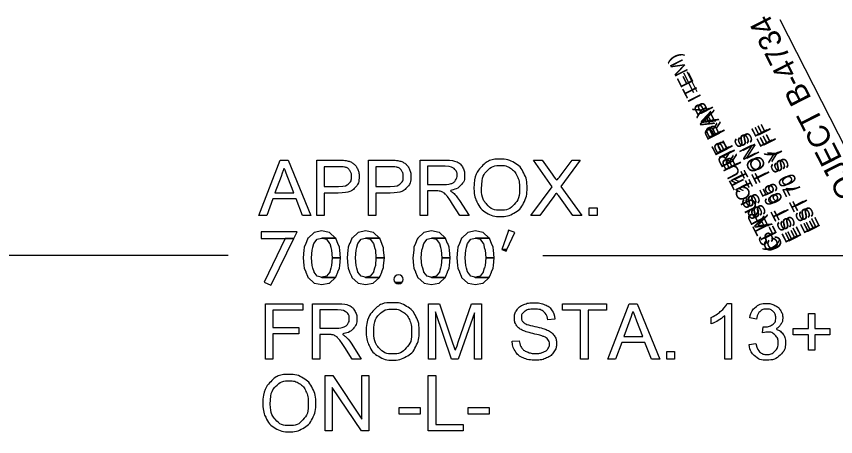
# Model space of a CAD drawing. Extents: x 557583 to 560285, y 513145 to 516544.
# Drawn here: x 558916.3 to 559211.5, y 515124.2 to 515275.7 of the extents above; entities that cross this region are included whole.
import ezdxf

# ---------------------------------------------------------------- set-up
doc = ezdxf.new("R2010")
doc.units = 0
for name, color, linetype in [('Default', 7, 'Continuous'), ('Prop Dimension', 7, 'Continuous'), ('Prop DSN Text', 7, 'Continuous'), ('Scratch_Level_0', 7, 'Continuous')]:
    doc.layers.add(name, color=color, linetype=linetype)

msp = doc.modelspace()

# ---------------------------------------------------------------- linework, layer by layer
at = {"layer": 'Default'}
for p, q in [((559160.44, 515248.11), (559156.81, 515255.24)), ((559161.62, 515248.55), (559157.99, 515255.68)), ((558992.61, 515189.47), (558699.28, 515189.47)), ((559105.95, 515189.47), (559399.28, 515189.47))]:
    msp.add_line(p, q, dxfattribs=at)
for points in [[(559003.66, 515203.89), (559011.35, 515223.89), (559014.22, 515223.89), (559022.38, 515203.89), (559019.37, 515203.89), (559017.05, 515209.94), (559008.66, 515209.94), (559006.47, 515203.89), (559003.66, 515203.89)], [(559011.64, 515217.96), (559009.43, 515212.09)], [(559009.43, 515212.09), (559016.22, 515212.09), (559014.13, 515217.64)], [(559005.99, 515152.12), (559005.99, 515172.12), (559019.49, 515172.12), (559019.49, 515169.76), (559008.64, 515169.76), (559008.64, 515163.57), (559018.03, 515163.57), (559018.03, 515161.2), (559008.64, 515161.2), (559008.64, 515152.12), (559005.99, 515152.12)], [(559027.57, 515126.23), (559027.57, 515146.23), (559030.28, 515146.23), (559040.8, 515130.53), (559040.8, 515146.23), (559043.33, 515146.23), (559043.33, 515126.23), (559040.62, 515126.23), (559030.1, 515141.94), (559030.1, 515126.23), (559027.57, 515126.23)]]:
    msp.add_lwpolyline(points, dxfattribs=at)
for points in [[(559014.13, 515217.64), (559013.18, 515220.17), (559012.72, 515221.78), (559012.32, 515219.86), (559011.64, 515217.96)], [(559005.06, 515135.98), (559005.06, 515140.95), (559007.73, 515143.77), (559010.4, 515146.59), (559014.63, 515146.59), (559017.4, 515146.59), (559019.63, 515145.26), (559021.85, 515143.94), (559023.02, 515141.57), (559024.19, 515139.21), (559024.19, 515136.21), (559024.19, 515133.17), (559022.96, 515130.77), (559021.73, 515128.37), (559019.48, 515127.13), (559017.23, 515125.9), (559014.62, 515125.9), (559011.8, 515125.9), (559009.57, 515127.26), (559007.35, 515128.63), (559006.2, 515130.99), (559005.06, 515133.34), (559005.06, 515135.98)], [(559007.78, 515135.94), (559007.78, 515132.33), (559009.73, 515130.25), (559011.67, 515128.17), (559014.61, 515128.17), (559017.6, 515128.17), (559019.53, 515130.27), (559021.46, 515132.37), (559021.46, 515136.23), (559021.46, 515138.67), (559020.63, 515140.49), (559019.81, 515142.31), (559018.22, 515143.31), (559016.63, 515144.31), (559014.65, 515144.31), (559011.84, 515144.31), (559009.81, 515142.38), (559007.78, 515140.46), (559007.78, 515135.94)]]:
    msp.add_open_spline(points, degree=3, dxfattribs=at)
at = {"layer": 'Prop Dimension'}
msp.add_line((559191.37, 515274.61), (559267.96, 515124.18), dxfattribs=at)
at = {"layer": 'Scratch_Level_0'}
for points in [[(559024.49, 515203.89), (559024.49, 515223.89), (559032.04, 515223.89)], [(559032.26, 515221.52), (559027.14, 515221.52), (559027.14, 515214.37)], [(559043.13, 515203.89), (559043.13, 515223.89), (559050.68, 515223.89)], [(559050.9, 515221.52), (559045.79, 515221.52), (559045.79, 515214.37)], [(559061.82, 515203.89), (559061.82, 515223.89), (559070.69, 515223.89)], [(559070.8, 515221.68), (559064.48, 515221.68), (559064.48, 515215.06)], [(559101.67, 515203.89), (559109.41, 515214.26), (559102.59, 515223.89), (559105.73, 515223.89), (559109.38, 515218.77)], [(559112.58, 515218.57), (559116.58, 515223.89), (559119.46, 515223.89), (559112.52, 515214.38), (559120.01, 515203.89), (559116.76, 515203.89), (559111.7, 515211.02)], [(559027.14, 515214.37), (559032.32, 515214.37)], [(559045.79, 515214.37), (559050.96, 515214.37)], [(559067.54, 515212.77), (559064.48, 515212.77), (559064.48, 515203.89), (559061.82, 515203.89)], [(559064.48, 515215.06), (559070.16, 515215.06)], [(559032.27, 515212.01), (559027.14, 515212.01), (559027.14, 515203.89), (559024.49, 515203.89)], [(559050.92, 515212.01), (559045.79, 515212.01), (559045.79, 515203.89), (559043.13, 515203.89)], [(559075.97, 515209.33), (559079.43, 515203.89), (559076.12, 515203.89), (559073.48, 515208.05)], [(559109.92, 515210.82), (559104.85, 515203.89), (559101.67, 515203.89)], [(559122.72, 515203.89), (559122.72, 515206.68), (559125.51, 515206.68), (559125.51, 515203.89), (559122.72, 515203.89)], [(559022.97, 515152.12), (559022.97, 515172.12), (559031.84, 515172.12)], [(559064.77, 515152.12), (559064.77, 515172.12), (559068.74, 515172.12), (559073.48, 515157.96)], [(559075.51, 515158.2), (559080.31, 515172.12), (559083.87, 515172.12), (559083.87, 515152.12), (559081.32, 515152.12), (559081.32, 515168.86), (559075.49, 515152.12), (559073.1, 515152.12), (559067.31, 515169.15), (559067.31, 515152.12), (559064.77, 515152.12)], [(559119.61, 515152.12), (559119.61, 515169.76), (559113.03, 515169.76), (559113.03, 515172.12), (559128.88, 515172.12), (559128.88, 515169.76), (559122.27, 515169.76), (559122.27, 515152.12), (559119.61, 515152.12)], [(559129.41, 515152.12), (559137.1, 515172.12), (559139.96, 515172.12), (559148.13, 515152.12), (559145.12, 515152.12), (559142.8, 515158.17), (559134.41, 515158.17), (559132.22, 515152.12), (559129.41, 515152.12)], [(559172.42, 515172.19), (559174, 515172.19), (559174, 515152.12)], [(559031.95, 515169.91), (559025.62, 515169.91), (559025.62, 515163.29)], [(559201.67, 515155.35), (559201.67, 515160.84), (559196.23, 515160.84), (559196.23, 515163.12), (559201.67, 515163.12), (559201.67, 515168.57), (559203.99, 515168.57), (559203.99, 515163.12), (559209.43, 515163.12), (559209.43, 515160.84), (559203.99, 515160.84), (559203.99, 515155.35), (559201.67, 515155.35)], [(559110.31, 515166.49), (559107.78, 515166.3)], [(559137.39, 515166.19), (559135.18, 515160.32)], [(559135.18, 515160.32), (559141.97, 515160.32), (559139.87, 515165.87)], [(559166.64, 515164.8), (559166.64, 515167.18)], [(559174, 515152.12), (559171.55, 515152.12), (559171.55, 515167.76)], [(559183.01, 515166.57), (559180.56, 515167.01)], [(559025.62, 515163.29), (559031.31, 515163.29)], [(559185.16, 515161.6), (559185.43, 515163.75)], [(559028.69, 515161.01), (559025.62, 515161.01), (559025.62, 515152.12), (559022.97, 515152.12)], [(559037.11, 515157.56), (559040.57, 515152.12), (559037.27, 515152.12), (559034.62, 515156.28)], [(559094.98, 515158.55), (559097.48, 515158.76)], [(559180.31, 515157.42), (559182.77, 515157.74)], [(559150.62, 515152.12), (559150.62, 515154.91), (559153.41, 515154.91), (559153.41, 515152.12), (559150.62, 515152.12)], [(559064.72, 515126.23), (559064.72, 515146.23), (559067.37, 515146.23), (559067.37, 515128.6), (559077.22, 515128.6), (559077.22, 515126.23), (559064.72, 515126.23)], [(559054.25, 515132.24), (559054.25, 515134.71), (559061.81, 515134.71), (559061.81, 515132.24), (559054.25, 515132.24)], [(559079.08, 515132.24), (559079.08, 515134.71), (559086.64, 515134.71), (559086.64, 515132.24), (559079.08, 515132.24)]]:
    msp.add_lwpolyline(points, dxfattribs=at)
for points in [[(559004.52, 515198.02), (559004.52, 515195.59), (559016.24, 515195.59), (559017.42, 515198.02)], [(559023.67, 515179.53), (559026.33, 515178.99), (559028.92, 515179.53), (559029.07, 515179.56), (559031.28, 515181.59), (559026.29, 515181.59), (559026.16, 515181.62), (559026.09, 515181.64), (559024.7, 515182.03), (559023.54, 515183.54), (559023.53, 515183.55), (559023.53, 515183.55), (559023.16, 515184.9), (559023.16, 515184.92), (559022.89, 515185.89), (559022.88, 515185.95), (559022.64, 515188.65), (559022.64, 515188.68), (559022.64, 515188.71), (559022.88, 515191.4), (559023.15, 515192.43), (559023.16, 515192.46), (559023.51, 515193.77), (559023.52, 515193.81), (559024.7, 515195.33), (559026.2, 515195.72), (559026.25, 515195.74), (559026.39, 515195.77), (559031.32, 515195.77), (559029.15, 515197.77), (559029.04, 515197.79), (559026.36, 515198.38), (559026.36, 515198.38), (559023.58, 515197.79), (559023.56, 515197.77), (559021.41, 515195.77), (559021.37, 515195.74), (559021.35, 515195.72), (559021.19, 515195.33), (559020.56, 515193.81), (559020.55, 515193.77), (559020.01, 515192.46), (559020, 515192.43), (559019.9, 515191.4), (559019.61, 515188.71), (559019.61, 515188.68), (559019.61, 515188.65), (559019.88, 515185.95), (559019.89, 515185.89), (559019.99, 515184.92), (559019.99, 515184.9), (559020.54, 515183.55), (559020.55, 515183.54), (559021.16, 515182.03), (559021.32, 515181.64), (559021.33, 515181.62), (559021.37, 515181.59), (559023.63, 515179.56)], [(559039.49, 515179.53), (559042.15, 515178.99), (559044.74, 515179.53), (559044.89, 515179.56), (559047.09, 515181.59), (559042.11, 515181.59), (559041.98, 515181.62), (559041.91, 515181.64), (559040.52, 515182.03), (559039.35, 515183.54), (559039.35, 515183.55), (559039.35, 515183.55), (559038.98, 515184.9), (559038.98, 515184.92), (559038.71, 515185.89), (559038.69, 515185.95), (559038.46, 515188.65), (559038.46, 515188.68), (559038.46, 515188.71), (559038.69, 515191.4), (559038.97, 515192.43), (559038.98, 515192.46), (559039.33, 515193.77), (559039.34, 515193.81), (559040.52, 515195.33), (559042.02, 515195.72), (559042.07, 515195.74), (559042.21, 515195.77), (559047.14, 515195.77), (559044.97, 515197.77), (559044.85, 515197.79), (559042.18, 515198.38), (559042.18, 515198.38), (559039.4, 515197.79), (559039.38, 515197.77), (559037.22, 515195.77), (559037.18, 515195.74), (559037.17, 515195.72), (559037.01, 515195.33), (559036.38, 515193.81), (559036.36, 515193.77), (559035.83, 515192.46), (559035.82, 515192.43), (559035.72, 515191.4), (559035.43, 515188.71), (559035.43, 515188.68), (559035.43, 515188.65), (559035.7, 515185.95), (559035.71, 515185.89), (559035.81, 515184.92), (559035.81, 515184.9), (559036.36, 515183.55), (559036.36, 515183.54), (559036.98, 515182.03), (559037.14, 515181.64), (559037.15, 515181.62), (559037.19, 515181.59), (559039.45, 515179.56)], [(559063.22, 515179.53), (559065.88, 515178.99), (559068.47, 515179.53), (559068.62, 515179.56), (559070.82, 515181.59), (559065.83, 515181.59), (559065.7, 515181.62), (559065.64, 515181.64), (559064.25, 515182.03), (559063.08, 515183.54), (559063.08, 515183.55), (559063.08, 515183.55), (559062.71, 515184.9), (559062.7, 515184.92), (559062.44, 515185.89), (559062.42, 515185.95), (559062.18, 515188.65), (559062.18, 515188.68), (559062.19, 515188.71), (559062.42, 515191.4), (559062.7, 515192.43), (559062.7, 515192.46), (559063.06, 515193.77), (559063.07, 515193.81), (559064.25, 515195.33), (559065.75, 515195.72), (559065.8, 515195.74), (559065.94, 515195.77), (559070.87, 515195.77), (559068.69, 515197.77), (559068.58, 515197.79), (559065.91, 515198.38), (559065.9, 515198.38), (559063.13, 515197.79), (559063.1, 515197.77), (559060.95, 515195.77), (559060.91, 515195.74), (559060.9, 515195.72), (559060.74, 515195.33), (559060.11, 515193.81), (559060.09, 515193.77), (559059.55, 515192.46), (559059.55, 515192.43), (559059.44, 515191.4), (559059.16, 515188.71), (559059.15, 515188.68), (559059.16, 515188.65), (559059.43, 515185.95), (559059.43, 515185.89), (559059.53, 515184.92), (559059.54, 515184.9), (559060.08, 515183.55), (559060.09, 515183.54), (559060.71, 515182.03), (559060.87, 515181.64), (559060.88, 515181.62), (559060.92, 515181.59), (559063.18, 515179.56)], [(559079.03, 515179.53), (559081.69, 515178.99), (559084.29, 515179.53), (559084.43, 515179.56), (559086.64, 515181.59), (559081.65, 515181.59), (559081.52, 515181.62), (559081.46, 515181.64), (559080.06, 515182.03), (559078.9, 515183.54), (559078.9, 515183.55), (559078.89, 515183.55), (559078.53, 515184.9), (559078.52, 515184.92), (559078.25, 515185.89), (559078.24, 515185.95), (559078, 515188.65), (559078, 515188.68), (559078.01, 515188.71), (559078.24, 515191.4), (559078.52, 515192.43), (559078.52, 515192.46), (559078.88, 515193.77), (559078.89, 515193.81), (559080.06, 515195.33), (559081.57, 515195.72), (559081.62, 515195.74), (559081.75, 515195.77), (559086.69, 515195.77), (559084.51, 515197.77), (559084.4, 515197.79), (559081.72, 515198.38), (559081.72, 515198.38), (559078.95, 515197.79), (559078.92, 515197.77), (559076.77, 515195.77), (559076.73, 515195.74), (559076.72, 515195.72), (559076.55, 515195.33), (559075.93, 515193.81), (559075.91, 515193.77), (559075.37, 515192.46), (559075.37, 515192.43), (559075.26, 515191.4), (559074.98, 515188.71), (559074.97, 515188.68), (559074.98, 515188.65), (559075.25, 515185.95), (559075.25, 515185.89), (559075.35, 515184.92), (559075.35, 515184.9), (559075.9, 515183.55), (559075.91, 515183.54), (559076.52, 515182.03), (559076.68, 515181.64), (559076.69, 515181.62), (559076.73, 515181.59), (559079, 515179.56)], [(559093.33, 515197.85), (559091.17, 515191.66), (559093.07, 515191.66), (559095.95, 515197.85), (559093.6, 515198.62)], [(559005.55, 515179.87), (559008.02, 515178.75), (559008.56, 515179.87), (559016.24, 515195.59), (559013.19, 515195.59)], [(559029.82, 515191.4), (559030.03, 515188.71), (559033.06, 515188.71), (559032.8, 515191.4), (559032.7, 515192.43), (559032.69, 515192.46), (559032.68, 515192.46), (559032.16, 515193.77), (559032.16, 515193.77), (559032.14, 515193.81), (559031.53, 515195.33), (559031.53, 515195.33), (559031.37, 515195.72), (559031.37, 515195.74), (559031.32, 515195.77), (559026.39, 515195.77), (559026.52, 515195.74), (559026.56, 515195.72), (559027.98, 515195.33), (559029.15, 515193.81), (559029.18, 515193.77), (559029.53, 515192.46), (559029.54, 515192.43)], [(559045.63, 515191.4), (559045.85, 515188.71), (559048.88, 515188.71), (559048.62, 515191.4), (559048.52, 515192.43), (559048.51, 515192.46), (559048.5, 515192.46), (559047.98, 515193.77), (559047.98, 515193.77), (559047.96, 515193.81), (559047.35, 515195.33), (559047.35, 515195.33), (559047.19, 515195.72), (559047.18, 515195.74), (559047.14, 515195.77), (559042.21, 515195.77), (559042.34, 515195.74), (559042.38, 515195.72), (559043.8, 515195.33), (559044.97, 515193.81), (559045, 515193.77), (559045.35, 515192.46), (559045.36, 515192.43)], [(559069.36, 515191.4), (559069.58, 515188.71), (559072.61, 515188.71), (559072.34, 515191.4), (559072.25, 515192.43), (559072.23, 515192.46), (559072.23, 515192.46), (559071.71, 515193.77), (559071.7, 515193.77), (559071.69, 515193.81), (559071.08, 515195.33), (559071.07, 515195.33), (559070.92, 515195.72), (559070.91, 515195.74), (559070.87, 515195.77), (559065.94, 515195.77), (559066.07, 515195.74), (559066.11, 515195.72), (559067.53, 515195.33), (559068.7, 515193.81), (559068.73, 515193.77), (559069.08, 515192.46), (559069.08, 515192.43)], [(559085.18, 515191.4), (559085.4, 515188.71), (559088.42, 515188.71), (559088.16, 515191.4), (559088.06, 515192.43), (559088.05, 515192.46), (559088.05, 515192.46), (559087.52, 515193.77), (559087.52, 515193.77), (559087.51, 515193.81), (559086.89, 515195.33), (559086.89, 515195.33), (559086.73, 515195.72), (559086.73, 515195.74), (559086.69, 515195.77), (559081.75, 515195.77), (559081.88, 515195.74), (559081.93, 515195.72), (559083.35, 515195.33), (559084.52, 515193.81), (559084.55, 515193.77), (559084.9, 515192.46), (559084.9, 515192.43)], [(559091.17, 515191.66), (559092.8, 515191.08), (559093.07, 515191.66)], [(559026.42, 515181.62), (559026.29, 515181.59), (559031.28, 515181.59), (559031.32, 515181.62), (559031.34, 515181.64), (559031.5, 515182.03), (559032.12, 515183.54), (559032.13, 515183.55), (559032.68, 515184.9), (559032.69, 515184.92), (559032.79, 515185.89), (559032.79, 515185.95), (559033.06, 515188.65), (559033.06, 515188.68), (559033.06, 515188.71), (559030.03, 515188.71), (559030.03, 515188.68), (559030.03, 515188.65), (559029.81, 515185.95), (559029.81, 515185.89), (559029.55, 515184.92), (559029.54, 515184.9), (559029.18, 515183.55), (559029.17, 515183.54), (559027.98, 515182.03), (559026.49, 515181.64)], [(559042.24, 515181.62), (559042.11, 515181.59), (559047.09, 515181.59), (559047.13, 515181.62), (559047.15, 515181.64), (559047.32, 515182.03), (559047.94, 515183.54), (559047.95, 515183.55), (559048.5, 515184.9), (559048.51, 515184.92), (559048.61, 515185.89), (559048.61, 515185.95), (559048.88, 515188.65), (559048.88, 515188.68), (559048.88, 515188.71), (559045.85, 515188.71), (559045.85, 515188.68), (559045.85, 515188.65), (559045.63, 515185.95), (559045.63, 515185.89), (559045.36, 515184.92), (559045.36, 515184.9), (559045, 515183.55), (559044.98, 515183.54), (559043.8, 515182.03), (559042.31, 515181.64)], [(559065.97, 515181.62), (559065.83, 515181.59), (559070.82, 515181.59), (559070.86, 515181.62), (559070.88, 515181.64), (559071.04, 515182.03), (559071.67, 515183.54), (559071.67, 515183.55), (559072.23, 515184.9), (559072.24, 515184.92), (559072.33, 515185.89), (559072.34, 515185.95), (559072.61, 515188.65), (559072.61, 515188.68), (559072.61, 515188.71), (559069.58, 515188.71), (559069.58, 515188.68), (559069.57, 515188.65), (559069.36, 515185.95), (559069.35, 515185.89), (559069.09, 515184.92), (559069.08, 515184.9), (559068.72, 515183.55), (559068.71, 515183.54), (559067.53, 515182.03), (559066.04, 515181.64)], [(559081.79, 515181.62), (559081.65, 515181.59), (559086.64, 515181.59), (559086.68, 515181.62), (559086.7, 515181.64), (559086.86, 515182.03), (559087.48, 515183.54), (559087.49, 515183.55), (559088.05, 515184.9), (559088.06, 515184.92), (559088.15, 515185.89), (559088.16, 515185.95), (559088.42, 515188.65), (559088.43, 515188.68), (559088.42, 515188.71), (559085.39, 515188.71), (559085.39, 515188.68), (559085.39, 515188.65), (559085.18, 515185.95), (559085.17, 515185.89), (559084.91, 515184.92), (559084.9, 515184.9), (559084.54, 515183.55), (559084.53, 515183.54), (559083.35, 515182.03), (559081.86, 515181.64)], [(559052.47, 515180.26), (559052.83, 515179.72), (559055.2, 515179.72), (559055.56, 515180.26), (559055.69, 515180.89), (559055.56, 515181.54), (559055.2, 515182.08), (559054.66, 515182.43), (559054.02, 515182.56), (559053.37, 515182.43), (559052.83, 515182.08), (559052.47, 515181.54), (559052.34, 515180.89)], [(559053.37, 515179.35), (559054.02, 515179.23), (559054.66, 515179.35), (559055.2, 515179.72), (559052.83, 515179.72)]]:
    msp.add_lwpolyline(points, close=True, dxfattribs=at)
for points in [[(559081.17, 515213.63), (559081.17, 515218.61), (559083.84, 515221.42), (559086.52, 515224.24), (559090.75, 515224.24), (559093.52, 515224.24), (559095.74, 515222.91), (559097.97, 515221.59), (559099.13, 515219.23), (559100.3, 515216.86), (559100.3, 515213.86), (559100.3, 515210.82), (559099.07, 515208.42), (559097.84, 515206.02), (559095.59, 515204.79), (559093.34, 515203.55), (559090.73, 515203.55), (559087.91, 515203.55), (559085.68, 515204.92), (559083.46, 515206.28), (559082.31, 515208.64), (559081.17, 515211), (559081.17, 515213.63)], [(559032.04, 515223.89), (559034.03, 515223.89), (559035.08, 515223.7), (559036.56, 515223.45), (559037.55, 515222.76), (559038.55, 515222.07), (559039.16, 515220.83), (559039.77, 515219.59), (559039.77, 515218.1), (559039.77, 515215.55), (559038.14, 515213.78), (559036.52, 515212.01), (559032.27, 515212.01)], [(559032.32, 515214.37), (559034.88, 515214.37), (559035.96, 515215.33), (559037.04, 515216.28), (559037.04, 515218.02), (559037.04, 515219.27), (559036.4, 515220.17), (559035.77, 515221.06), (559034.73, 515221.35), (559034.06, 515221.52), (559032.26, 515221.52)], [(559050.68, 515223.89), (559052.68, 515223.89), (559053.73, 515223.7), (559055.2, 515223.45), (559056.2, 515222.76), (559057.19, 515222.07), (559057.8, 515220.83), (559058.41, 515219.59), (559058.41, 515218.1), (559058.41, 515215.55), (559056.79, 515213.78), (559055.16, 515212.01), (559050.92, 515212.01)], [(559050.96, 515214.37), (559053.52, 515214.37), (559054.6, 515215.33), (559055.68, 515216.28), (559055.68, 515218.02), (559055.68, 515219.27), (559055.05, 515220.17), (559054.41, 515221.06), (559053.37, 515221.35), (559052.71, 515221.52), (559050.9, 515221.52)], [(559070.16, 515215.06), (559071.98, 515215.06), (559073, 515215.44), (559074.02, 515215.81), (559074.55, 515216.64), (559075.09, 515217.46), (559075.09, 515218.43), (559075.09, 515219.85), (559074.06, 515220.76), (559073.03, 515221.68), (559070.8, 515221.68)], [(559070.69, 515223.89), (559073.37, 515223.89), (559074.76, 515223.35), (559076.15, 515222.81), (559076.98, 515221.45), (559077.81, 515220.08), (559077.81, 515218.43), (559077.81, 515216.3), (559076.44, 515214.84), (559075.06, 515213.38), (559072.18, 515212.99), (559073.23, 515212.48), (559073.78, 515211.99), (559074.94, 515210.93), (559075.97, 515209.33)], [(559083.9, 515213.59), (559083.9, 515209.98), (559085.84, 515207.9), (559087.79, 515205.82), (559090.72, 515205.82), (559093.71, 515205.82), (559095.64, 515207.92), (559097.57, 515210.02), (559097.57, 515213.88), (559097.57, 515216.32), (559096.74, 515218.14), (559095.92, 515219.96), (559094.33, 515220.96), (559092.74, 515221.97), (559090.76, 515221.97), (559087.95, 515221.97), (559085.92, 515220.04), (559083.9, 515218.11), (559083.9, 515213.59)], [(559109.38, 515218.77), (559110.52, 515217.18), (559110.99, 515216.31), (559111.66, 515217.38), (559112.58, 515218.57)], [(559073.48, 515208.05), (559072.32, 515209.85), (559071.57, 515210.8), (559070.82, 515211.76), (559070.22, 515212.14), (559069.63, 515212.53), (559069.02, 515212.68), (559068.57, 515212.77), (559067.54, 515212.77)], [(559111.7, 515211.02), (559111.27, 515211.63), (559110.87, 515212.25), (559110.21, 515211.23), (559109.92, 515210.82)], [(559031.84, 515172.12), (559034.51, 515172.12), (559035.9, 515171.58), (559037.29, 515171.04), (559038.13, 515169.68), (559038.96, 515168.31), (559038.96, 515166.66), (559038.96, 515164.53), (559037.58, 515163.07), (559036.2, 515161.61), (559033.33, 515161.22), (559034.38, 515160.71), (559034.92, 515160.22), (559036.08, 515159.16), (559037.11, 515157.56)], [(559042.31, 515161.86), (559042.31, 515166.84), (559044.99, 515169.65), (559047.66, 515172.47), (559051.89, 515172.47), (559054.66, 515172.47), (559056.88, 515171.15), (559059.11, 515169.82), (559060.28, 515167.46), (559061.44, 515165.09), (559061.44, 515162.09), (559061.44, 515159.05), (559060.21, 515156.65), (559058.99, 515154.25), (559056.73, 515153.02), (559054.48, 515151.78), (559051.88, 515151.78), (559049.05, 515151.78), (559046.83, 515153.15), (559044.6, 515154.51), (559043.46, 515156.87), (559042.31, 515159.23), (559042.31, 515161.86)], [(559097.48, 515158.76), (559097.66, 515157.26), (559098.31, 515156.3), (559098.95, 515155.33), (559100.32, 515154.74), (559101.69, 515154.15), (559103.39, 515154.15), (559104.91, 515154.15), (559106.07, 515154.6), (559107.23, 515155.05), (559107.8, 515155.83), (559108.36, 515156.62), (559108.36, 515157.55), (559108.36, 515158.49), (559107.82, 515159.19), (559107.28, 515159.9), (559106.02, 515160.37), (559105.21, 515160.69), (559102.44, 515161.35), (559099.67, 515162.01), (559098.56, 515162.6), (559097.13, 515163.35), (559096.43, 515164.46), (559095.73, 515165.57), (559095.73, 515166.95), (559095.73, 515168.47), (559096.59, 515169.79), (559097.45, 515171.1), (559099.1, 515171.79), (559100.76, 515172.47), (559102.78, 515172.47), (559105.01, 515172.47), (559106.71, 515171.75), (559108.41, 515171.04), (559109.33, 515169.65), (559110.25, 515168.25), (559110.31, 515166.49)], [(559166.64, 515167.18), (559168.7, 515168.14), (559170.24, 515169.52), (559171.78, 515170.9), (559172.42, 515172.19)], [(559180.56, 515167.01), (559181.01, 515169.48), (559182.61, 515170.84), (559184.2, 515172.19), (559186.58, 515172.19), (559188.22, 515172.19), (559189.59, 515171.49), (559190.97, 515170.79), (559191.7, 515169.58), (559192.43, 515168.37), (559192.43, 515167.01), (559192.43, 515165.71), (559191.74, 515164.65), (559191.04, 515163.59), (559189.68, 515162.96), (559191.45, 515162.55), (559192.43, 515161.26), (559193.41, 515159.98), (559193.41, 515158.04), (559193.41, 515155.42), (559191.5, 515153.6), (559189.59, 515151.78), (559186.67, 515151.78), (559184.04, 515151.78), (559182.3, 515153.35), (559180.56, 515154.92), (559180.31, 515157.42)], [(559031.31, 515163.29), (559033.12, 515163.29), (559034.14, 515163.67), (559035.17, 515164.04), (559035.7, 515164.87), (559036.23, 515165.69), (559036.23, 515166.66), (559036.23, 515168.08), (559035.2, 515168.99), (559034.17, 515169.91), (559031.95, 515169.91)], [(559045.04, 515161.83), (559045.04, 515158.21), (559046.98, 515156.13), (559048.93, 515154.05), (559051.86, 515154.05), (559054.85, 515154.05), (559056.78, 515156.15), (559058.71, 515158.25), (559058.71, 515162.11), (559058.71, 515164.55), (559057.89, 515166.37), (559057.06, 515168.19), (559055.47, 515169.2), (559053.88, 515170.2), (559051.9, 515170.2), (559049.09, 515170.2), (559047.07, 515168.27), (559045.04, 515166.34), (559045.04, 515161.83)], [(559107.78, 515166.3), (559107.58, 515168.2), (559106.39, 515169.17), (559105.21, 515170.14), (559102.89, 515170.14), (559100.48, 515170.14), (559099.38, 515169.26), (559098.27, 515168.38), (559098.27, 515167.13), (559098.27, 515166.05), (559099.05, 515165.36), (559099.82, 515164.66), (559103.06, 515163.93), (559106.3, 515163.2), (559107.5, 515162.65), (559109.25, 515161.85), (559110.08, 515160.62), (559110.91, 515159.38), (559110.91, 515157.77), (559110.91, 515156.18), (559109.99, 515154.76), (559109.08, 515153.35), (559107.37, 515152.57), (559105.65, 515151.78), (559103.51, 515151.78), (559100.79, 515151.78), (559098.96, 515152.57), (559097.12, 515153.37), (559096.08, 515154.96), (559095.03, 515156.55), (559094.98, 515158.55)], [(559139.87, 515165.87), (559138.93, 515168.4), (559138.46, 515170.01), (559138.07, 515168.1), (559137.39, 515166.19)], [(559185.43, 515163.75), (559185.67, 515163.72), (559185.82, 515163.72), (559187.39, 515163.72), (559188.65, 515164.54), (559189.9, 515165.36), (559189.9, 515167.06), (559189.9, 515168.41), (559188.99, 515169.3), (559188.07, 515170.18), (559186.63, 515170.18), (559185.2, 515170.18), (559184.24, 515169.28), (559183.29, 515168.38), (559183.01, 515166.57)], [(559171.55, 515167.76), (559170.66, 515166.92), (559169.22, 515166.07), (559167.79, 515165.23), (559166.64, 515164.8)], [(559034.62, 515156.28), (559033.46, 515158.08), (559032.71, 515159.04), (559031.96, 515159.99), (559031.37, 515160.38), (559030.77, 515160.76), (559030.16, 515160.91), (559029.71, 515161.01), (559028.69, 515161.01)], [(559182.77, 515157.74), (559183.19, 515155.65), (559184.2, 515154.73), (559185.22, 515153.81), (559186.68, 515153.81), (559188.42, 515153.81), (559189.61, 515155.01), (559190.8, 515156.21), (559190.8, 515157.99), (559190.8, 515159.68), (559189.7, 515160.78), (559188.59, 515161.87), (559186.89, 515161.87), (559186.19, 515161.87), (559185.16, 515161.6)], [(559073.48, 515157.96), (559074.14, 515155.98), (559074.44, 515155), (559074.78, 515156.09), (559075.51, 515158.2)]]:
    msp.add_open_spline(points, degree=3, dxfattribs=at)

# ---------------------------------------------------------------- texts
at = {"layer": 'Default'}
for s, p in [('CLASS 11 RIP RAP', (559192.77, 515192.89)), ('CLASS 11 RIP RAP', (559191.58, 515192.45)), ('EST 70 SY FF', (559204.95, 515199.26)), ('EST 70 SY FF', (559206.13, 515199.69)), ('EST 65 TONS', (559198.27, 515195.86)), ('EST 65 TONS', (559199.45, 515196.29))]:
    msp.add_text(s, height=5, rotation=116.9819, dxfattribs=at).set_placement(p)
at = {"layer": 'Prop Dimension'}
msp.add_text('(STRUCTURE PAY ITEM) ', height=5, rotation=116.9819, dxfattribs=at).set_placement((559190.69, 515192.59))
at = {"layer": 'Prop DSN Text'}
msp.add_text('BEGIN PROJECT B-4734', height=8, rotation=116.9819, dxfattribs=at).set_placement((559243.4, 515166.63))

doc.saveas('drawing.dxf')
